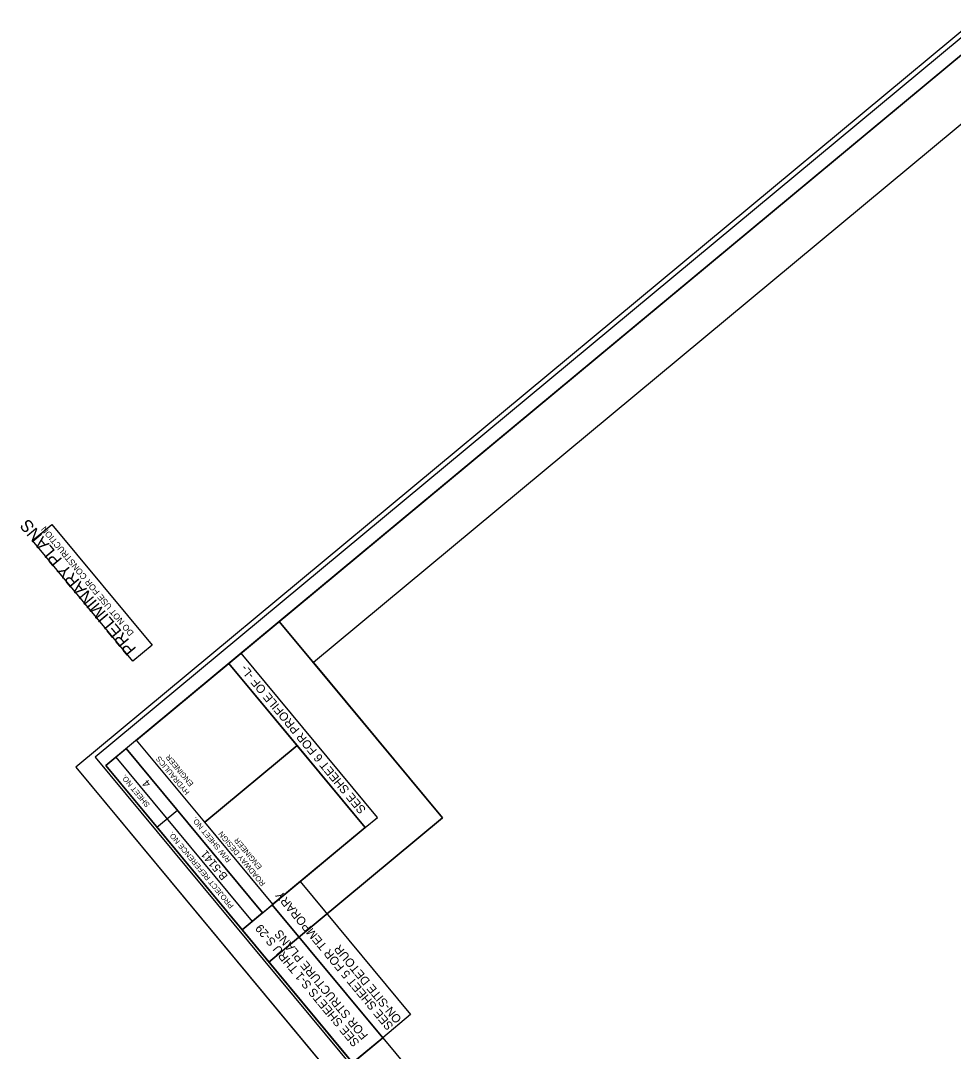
# Model space of a CAD drawing. Extents: x 2597026 to 2598995, y 852197 to 854192.
# Drawn here: x 2597026 to 2597900, y 853226 to 854192 of the extents above; entities that cross this region are included whole.
import ezdxf

# ---------------------------------------------------------------- set-up
doc = ezdxf.new("R2010")
doc.units = 0
for name, color, linetype in [('Default', 7, 'Continuous'), ('Old_Level_1', 7, 'Continuous'), ('Old_Level_2', 7, 'Continuous'), ('Prop Dimension Text', 7, 'Continuous'), ('Sheet Clip Boundary CELL', 7, 'Continuous'), ('Sheet Cutting Line CELL', 7, 'Continuous'), ('Sheet Data Field CELL', 7, 'Continuous'), ('Sheet Plan CELL', 7, 'Continuous'), ('Sheet Plan Layout CELL', 7, 'Continuous'), ('Sheet Plot Border Inside CELL', 7, 'Continuous'), ('Sheet Plot Border Outside CELL', 7, 'Continuous'), ('Sheet Sticker Preliminary CELL', 7, 'Continuous')]:
    doc.layers.add(name, color=color, linetype=linetype)

msp = doc.modelspace()

# ---------------------------------------------------------------- linework, layer by layer
at = {"layer": 'Default'}
for points in [[(2597365.22, 853238.27), (2597261.67, 853362.96), (2597287.82, 853384.67), (2597391.37, 853259.98)], [(2597336.88, 853214.74), (2597233.33, 853339.43), (2597261.67, 853362.96), (2597365.22, 853238.27)]]:
    msp.add_lwpolyline(points, close=True, dxfattribs=at)
at = {"layer": 'Prop Dimension Text'}
msp.add_lwpolyline([(2597442.61, 853088.71), (2597337.52, 853215.26), (2597365.22, 853238.27), (2597470.31, 853111.71)], close=True, dxfattribs=at)
at = {"layer": 'Sheet Clip Boundary CELL'}
msp.add_lwpolyline([(2598839.68, 853048.61), (2597945.27, 854125.68), (2597300.19, 853589.99), (2597421.1, 853444.38), (2597258.39, 853309.27), (2598031.89, 852377.81)], close=True, dxfattribs=at)
at = {"layer": 'Sheet Cutting Line CELL'}
msp.add_line((2597077.38, 853492.06), (2598152.9, 852196.9), dxfattribs=at)
at = {"layer": 'Sheet Plan CELL'}
for p, q in [((2597360.31, 853444.89), (2597232.53, 853598.79)), ((2597348.77, 853435.31), (2597220.99, 853589.21)), ((2597252.63, 853355.46), (2597124.82, 853509.34)), ((2597252.63, 853355.46), (2597124.82, 853509.34)), ((2597198.32, 853440.41), (2597284.84, 853512.27)), ((2597243, 853347.44), (2597115.2, 853501.35)), ((2597153.53, 853435.66), (2597172.73, 853451.67)), ((2597348.77, 853435.31), (2597360.31, 853444.89)), ((2597252.63, 853355.46), (2597262.24, 853363.44))]:
    msp.add_line(p, q, dxfattribs=at)
for points in [[(2597105.52, 853493.36), (2598063.83, 852339.35), (2598871.63, 853010.15), (2597913.33, 854164.14)], [(2598871.63, 853010.15), (2598063.87, 852339.34), (2597233.33, 853339.43), (2597348.77, 853435.31), (2597220.99, 853589.21), (2597913.33, 854164.14)], [(2597198.32, 853440.41), (2597134.44, 853517.32), (2597220.99, 853589.21), (2597284.88, 853512.29)], [(2597233.33, 853339.43), (2597105.52, 853493.36), (2597124.82, 853509.34), (2597252.63, 853355.46)], [(2597262.24, 853363.44), (2597198.32, 853440.41), (2597284.88, 853512.29), (2597348.77, 853435.31)]]:
    msp.add_lwpolyline(points, close=True, dxfattribs=at)
at = {"layer": 'Sheet Plan Layout CELL'}
for points in [[(2598063.87, 852339.34), (2598871.63, 853010.15), (2597913.34, 854164.13), (2597268.25, 853628.44), (2597421.1, 853444.38), (2597258.39, 853309.27)], [(2597421.1, 853444.38), (2597268.23, 853628.46), (2597105.52, 853493.37), (2597258.39, 853309.27)]]:
    msp.add_lwpolyline(points, close=True, dxfattribs=at)
at = {"layer": 'Sheet Plot Border Inside CELL'}
msp.add_lwpolyline([(2598971.62, 852893.67), (2597907.28, 854175.35), (2597095.64, 853501.37), (2598159.98, 852219.68)], close=True, dxfattribs=at)
at = {"layer": 'Sheet Plot Border Outside CELL'}
msp.add_lwpolyline([(2598995.31, 852896.45), (2597919.79, 854191.6), (2597077.38, 853492.06), (2598152.9, 852196.9)], close=True, dxfattribs=at)
at = {"layer": 'Sheet Sticker Preliminary CELL'}
msp.add_lwpolyline([(2597148.98, 853606.28), (2597130.9, 853591.27), (2597036.99, 853704.36), (2597055.07, 853719.37)], close=True, dxfattribs=at)

# ---------------------------------------------------------------- texts
at = {"layer": 'Old_Level_1'}
for s, p in [('SEE SHEET 6 FOR PROFILE OF -L-', (2597349.99, 853452.28)), ('SEE SHEETS S-1 THRU S-29   ', (2597343.9, 853233.99)), ('FOR STRUCTURE PLANS', (2597351.97, 853240.69))]:
    msp.add_text(s, height=8, rotation=129.70674, dxfattribs=at).set_placement(p)
at = {"layer": 'Old_Level_2'}
for s, p in [('SEE SHEET 5 FOR TEMPORARY ', (2597375.68, 853249.52)), ('ON-SITE DETOUR', (2597383.43, 853255.96))]:
    msp.add_text(s, height=8, rotation=129.70666, dxfattribs=at).set_placement(p)
at = {"layer": 'Sheet Data Field CELL'}
for s, p in [('4', (2597148.36, 853476.61)), ('B-5141', (2597220.39, 853389.96))]:
    msp.add_text(s, height=7.5, rotation=129.7067, dxfattribs=at).set_placement(p)
at = {"layer": 'Sheet Plan CELL'}
for s, height, p in [('HYDRAULICS', 5, (2597184.46, 853468.49)), ('ENGINEER', 5, (2597188.18, 853476.47)), ('SHEET NO.', 5, (2597147.27, 853456.91)), ('R/W SHEET NO.', 5.0001, (2597223.29, 853405.18)), ('PROJECT REFERENCE NO.', 5.0001, (2597225.86, 853362.09)), ('ROADWAY DESIGN', 5.0001, (2597255.48, 853383.01)), ('ENGINEER', 5, (2597252.34, 853398.58))]:
    msp.add_text(s, height=height, rotation=129.7067, dxfattribs=at).set_placement(p)
at = {"layer": 'Sheet Sticker Preliminary CELL'}
for s, height, p in [('PRELIMINARY PLANS', 11.52, (2597134.71, 853602.88)), ('DO NOT USE FOR CONSTRUCTION', 5.76, (2597132.27, 853617.88))]:
    msp.add_text(s, height=height, rotation=129.70669, dxfattribs=at).set_placement(p)

doc.saveas('drawing.dxf')
